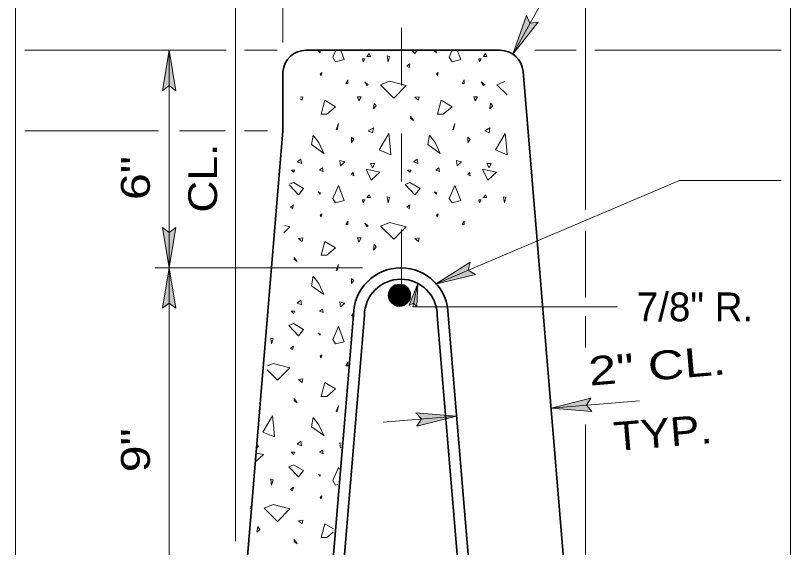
# Model space of a CAD drawing. Extents: x -9.07 to -2.08, y 8.04 to 17.77.
# Drawn here: x -6.811 to -5.197, y 15.562 to 16.67 of the extents above; entities that cross this region are included whole.
import ezdxf
from ezdxf.enums import TextEntityAlignment as Align

# ---------------------------------------------------------------- set-up
doc = ezdxf.new("R2010")
doc.units = 0
doc.header["$LTSCALE"] = 0.024
doc.linetypes.add('DOT_DASHED', pattern=[7.7, 5, -1.2, 0.3, -1.2])
for name, color, linetype, lineweight in [('1', 7, 'Continuous', 35), ('10', 7, 'Continuous', 13), ('12', 7, 'Continuous', 53), ('6', 7, 'Continuous', 13)]:
    doc.layers.add(name, color=color, linetype=linetype, lineweight=lineweight)

msp = doc.modelspace()

# ---------------------------------------------------------------- hatches: boundary and pattern name
at = {"layer": '10'}
for points in [[(-5.77533, 16.58917), (-5.72233, 16.65583), (-5.73967, 16.6535), (-5.74667, 16.66933)], [(-6.491, 16.59717), (-6.477, 16.51317), (-6.491, 16.52367), (-6.505, 16.51317)], [(-6.491, 16.14433), (-6.477, 16.22833), (-6.491, 16.21783), (-6.505, 16.22833)], [(-5.86433, 16.15633), (-5.93617, 16.11067), (-5.85333, 16.13067), (-5.8685, 16.1395)], [(-6.491, 16.14433), (-6.477, 16.06033), (-6.491, 16.07083), (-6.505, 16.06033)], [(-5.97333, 16.11167), (-5.97533, 16.063), (-5.982, 16.0705), (-5.991, 16.06633)], [(-5.6955, 15.85217), (-5.613, 15.87317), (-5.62233, 15.85833), (-5.61067, 15.84517)], [(-5.97733, 15.84267), (-5.89233, 15.83567), (-5.975, 15.81483), (-5.96567, 15.82967)]]:
    msp.add_hatch(color=256, dxfattribs=at).paths.add_polyline_path(points)

# ---------------------------------------------------------------- linework, layer by layer
at = {"layer": '1'}
for p, q in [((-6.206, 16.59717), (-5.80183, 16.59717)), ((-5.754, 16.55317), (-5.66, 15.4245)), ((-6.284, 13.922), (-6.107, 16.04583)), ((-6.26133, 13.922), (-6.08433, 16.04483)), ((-5.93267, 16.04483), (-5.75567, 13.922)), ((-5.91, 16.04583), (-5.73283, 13.922))]:
    msp.add_line(p, q, dxfattribs=at)
msp.add_lwpolyline([(-6.348, 15.30083), (-6.25383, 16.42933), (-6.25383, 16.55317)], dxfattribs=at)
for centre, radius in [((-6.01135, 16.08716), 0.02253), ((-6.01154, 16.08735), 0.02103), ((-6.01356, 16.08735), 0.01823), ((-6.01129, 16.08681), 0.02028), ((-6.01069, 16.08586), 0.01988), ((-6.01079, 16.08657), 0.0185), ((-6.01281, 16.08823), 0.01508), ((-6.0103, 16.08646), 0.01751), ((-6.01016, 16.08596), 0.0166), ((-6.00991, 16.08572), 0.01584), ((-6.01317, 16.08646), 0.01309), ((-6.01016, 16.08533), 0.0151), ((-6.0143, 16.08572), 0.01045), ((-6.00977, 16.08533), 0.01471), ((-6.01005, 16.08557), 0.01421), ((-6.00941, 16.08522), 0.01358), ((-6.00927, 16.08547), 0.01272), ((-6.01257, 16.08621), 0.00844), ((-6.00916, 16.08561), 0.01184), ((-6.00916, 16.08586), 0.01085), ((-6.00902, 16.08557), 0.01021), ((-6.00902, 16.08547), 0.00921), ((-6.00863, 16.08469), 0.00882), ((-6.00842, 16.08458), 0.00805), ((-6.00842, 16.08479), 0.00706), ((-6.00814, 16.08497), 0.00681), ((-6.00814, 16.08433), 0.00627), ((-6.00789, 16.08483), 0.00602), ((-6.00778, 16.08469), 0.00515), ((-6.00814, 16.08508), 0.0043), ((-6.00764, 16.08455), 0.00382), ((-6.0075, 16.08458), 0.00316), ((-6.00725, 16.08444), 0.00241), ((-6.00725, 16.08469), 0.00213), ((-6.00651, 16.08458), 0.00267), ((-6.00729, 16.08469), 0.00139), ((-6.00753, 16.08469), 0.000653), ((-6.007, 16.08469), 0.000415)]:
    msp.add_circle(centre, radius, dxfattribs=at)
for centre, radius, start, end in [((-6.20603, 16.54913), 0.04804, 90, 175.23532), ((-5.80188, 16.54913), 0.04804, 4.76467, 89.99999), ((-6.00847, 16.04581), 0.09853, 0, 180), ((-6.00847, 16.04487), 0.07581, 0, 180)]:
    msp.add_arc(centre, radius, start, end, dxfattribs=at)
at = {"layer": '10'}
for p, q in [((-6.81067, 17.69383), (-6.81067, 14.55983)), ((-5.624, 16.26517), (-5.624, 17.23967)), ((-5.67767, 16.765), (-5.77533, 16.58917)), ((-5.19733, 16.59683), (-5.19733, 16.705)), ((-5.74667, 16.66933), (-5.77533, 16.58917)), ((-5.74667, 16.66933), (-5.73967, 16.6535)), ((-5.72233, 16.65583), (-5.77533, 16.58917)), ((-5.72233, 16.65583), (-5.73967, 16.6535)), ((-6.37217, 16.59717), (-6.7915, 16.59717)), ((-6.505, 16.51317), (-6.491, 16.59717)), ((-6.491, 16.14433), (-6.491, 16.59717)), ((-6.477, 16.51317), (-6.491, 16.59717)), ((-6.266, 16.59717), (-6.33367, 16.59717)), ((-5.72983, 16.59717), (-5.64317, 16.59717)), ((-5.60483, 16.59717), (-5.2165, 16.59717)), ((-5.19733, 14.70767), (-5.19733, 16.59683)), ((-6.505, 16.51317), (-6.491, 16.52367)), ((-6.477, 16.51317), (-6.491, 16.52367)), ((-6.51267, 16.42933), (-6.7915, 16.42933)), ((-6.3745, 16.42933), (-6.46933, 16.42933)), ((-6.286, 16.42933), (-6.33367, 16.42933)), ((-5.42833, 16.32633), (-5.93617, 16.11067)), ((-5.42833, 16.32633), (-5.2165, 16.32633)), ((-6.505, 16.22833), (-6.491, 16.14433)), ((-6.505, 16.22833), (-6.491, 16.21783)), ((-6.477, 16.22833), (-6.491, 16.14433)), ((-6.477, 16.22833), (-6.491, 16.21783)), ((-5.624, 16.08233), (-5.624, 16.22167)), ((-5.86433, 16.15633), (-5.93617, 16.11067)), ((-5.86433, 16.15633), (-5.8685, 16.1395)), ((-6.0885, 16.14433), (-6.51983, 16.14433)), ((-6.505, 16.06033), (-6.491, 16.14433)), ((-6.477, 16.06033), (-6.491, 16.14433)), ((-6.491, 16.14433), (-6.491, 15.376)), ((-5.85333, 16.13067), (-5.8685, 16.1395)), ((-5.85333, 16.13067), (-5.93617, 16.11067)), ((-5.991, 16.06633), (-5.97333, 16.11167)), ((-5.97533, 16.063), (-5.97333, 16.11167)), ((-6.505, 16.06033), (-6.491, 16.07083)), ((-6.477, 16.06033), (-6.491, 16.07083)), ((-5.991, 16.06633), (-5.982, 16.0705)), ((-5.97533, 16.063), (-5.982, 16.0705)), ((-5.624, 15.97867), (-5.624, 16.04383)), ((-5.613, 15.87317), (-5.6955, 15.85217)), ((-5.6955, 15.85217), (-5.5115, 15.8675)), ((-5.613, 15.87317), (-5.62233, 15.85833)), ((-5.61067, 15.84517), (-5.6955, 15.85217)), ((-5.61067, 15.84517), (-5.62233, 15.85833)), ((-6.045, 15.823), (-5.89233, 15.83567)), ((-5.97733, 15.84267), (-5.89233, 15.83567)), ((-5.97733, 15.84267), (-5.96567, 15.82967)), ((-5.975, 15.81483), (-5.89233, 15.83567)), ((-5.975, 15.81483), (-5.96567, 15.82967)), ((-5.624, 15.34), (-5.624, 15.8185))]:
    msp.add_line(p, q, dxfattribs=at)
at = {"layer": '10', "linetype": 'DOT_DASHED'}
msp.add_line((-6.00733, 16.10383), (-6.00733, 16.94883), dxfattribs=at)
at = {"layer": '10'}
for points in [[(-6.25383, 16.61317), (-6.25383, 16.707), (-6.25383, 17.4055)], [(-6.353, 17.23967), (-6.353, 16.5955), (-6.353, 15.57517)], [(-5.5575, 16.063), (-5.9835, 16.063), (-5.97333, 16.11167)]]:
    msp.add_lwpolyline(points, dxfattribs=at)
for points in [[(-5.77533, 16.58917), (-5.72233, 16.65583), (-5.73967, 16.6535), (-5.74667, 16.66933)], [(-6.491, 16.59717), (-6.477, 16.51317), (-6.491, 16.52367), (-6.505, 16.51317)], [(-6.491, 16.14433), (-6.477, 16.22833), (-6.491, 16.21783), (-6.505, 16.22833)], [(-5.86433, 16.15633), (-5.93617, 16.11067), (-5.85333, 16.13067), (-5.8685, 16.1395)], [(-6.491, 16.14433), (-6.477, 16.06033), (-6.491, 16.07083), (-6.505, 16.06033)], [(-5.97333, 16.11167), (-5.97533, 16.063), (-5.982, 16.0705), (-5.991, 16.06633)], [(-5.6955, 15.85217), (-5.613, 15.87317), (-5.62233, 15.85833), (-5.61067, 15.84517)], [(-5.97733, 15.84267), (-5.89233, 15.83567), (-5.975, 15.81483), (-5.96567, 15.82967)]]:
    msp.add_lwpolyline(points, close=True, dxfattribs=at)
at = {"layer": '6'}
for points in [[(-6.17633, 16.59467), (-6.1805, 16.59617), (-6.17633, 16.59183)], [(-6.07467, 16.59033), (-6.0715, 16.58433), (-6.079, 16.58433)], [(-6.03683, 16.58567), (-6.03517, 16.5735), (-6.03217, 16.58433)], [(-5.934, 16.59467), (-5.93833, 16.59617), (-5.934, 16.59183)], [(-5.83233, 16.59033), (-5.82917, 16.58433), (-5.83667, 16.58433)], [(-6.08833, 16.5795), (-6.087, 16.5735), (-6.08367, 16.5795)], [(-5.99583, 16.5645), (-5.9915, 16.5615), (-5.98967, 16.56917)], [(-5.846, 16.5795), (-5.84467, 16.5735), (-5.84133, 16.5795)], [(-6.173, 16.55083), (-6.17633, 16.54783), (-6.1745, 16.54467)], [(-5.93067, 16.55083), (-5.934, 16.54783), (-5.93217, 16.54467)], [(-6.11867, 16.53567), (-6.123, 16.52817), (-6.11867, 16.52817)], [(-6.079, 16.52383), (-6.07617, 16.52517), (-6.08367, 16.53133)], [(-6.03217, 16.53283), (-5.99733, 16.52383), (-6.02317, 16.49783), (-6.05067, 16.52517)], [(-5.87633, 16.53567), (-5.88067, 16.52817), (-5.87633, 16.52817)], [(-5.83667, 16.52383), (-5.83383, 16.52517), (-5.84133, 16.53133)], [(-6.1625, 16.46433), (-6.14417, 16.47983), (-6.16683, 16.49317), (-6.1745, 16.46433)], [(-6.09883, 16.50067), (-6.096, 16.49167), (-6.09133, 16.50067)], [(-5.97933, 16.49933), (-5.97167, 16.49317), (-5.97033, 16.50067)], [(-5.92033, 16.46433), (-5.90183, 16.47983), (-5.9245, 16.49317), (-5.93217, 16.46433)], [(-5.8565, 16.50067), (-5.85367, 16.49167), (-5.849, 16.50067)], [(-6.06383, 16.48733), (-6.06567, 16.47517), (-6.05967, 16.48133)], [(-5.82167, 16.48733), (-5.82333, 16.47517), (-5.81733, 16.48133)], [(-5.98833, 16.46), (-5.98833, 16.45533), (-5.98217, 16.451)], [(-6.14283, 16.43267), (-6.14133, 16.43267), (-6.1385, 16.44483)], [(-5.9005, 16.43267), (-5.899, 16.43267), (-5.89617, 16.44483)], [(-6.07617, 16.42983), (-6.06717, 16.42517), (-6.06567, 16.43583)], [(-5.83383, 16.42983), (-5.82483, 16.42517), (-5.82333, 16.43583)], [(-6.19133, 16.4205), (-6.19433, 16.401), (-6.16867, 16.38267), (-6.17917, 16.40533)], [(-6.111, 16.41617), (-6.111, 16.40533), (-6.10633, 16.4115)], [(-6.03083, 16.39767), (-6.02933, 16.37967), (-6.0535, 16.39017), (-6.03367, 16.42367)], [(-5.949, 16.4205), (-5.952, 16.401), (-5.92633, 16.38267), (-5.93683, 16.40533)], [(-5.86883, 16.41617), (-5.86883, 16.40533), (-5.864, 16.4115)], [(-5.7885, 16.39767), (-5.787, 16.37967), (-5.81117, 16.39017), (-5.79133, 16.42367)], [(-6.217, 16.37067), (-6.2245, 16.36467), (-6.2155, 16.36133)], [(-6.13517, 16.3675), (-6.13383, 16.357), (-6.12483, 16.36467)], [(-6.0715, 16.36133), (-6.06717, 16.35233), (-6.0625, 16.36133)], [(-5.97467, 16.37067), (-5.98217, 16.36467), (-5.97317, 16.36133)], [(-5.89283, 16.3675), (-5.8915, 16.357), (-5.8825, 16.36467)], [(-5.82917, 16.36133), (-5.82483, 16.35233), (-5.82017, 16.36133)], [(-6.17767, 16.348), (-6.17017, 16.34483), (-6.1715, 16.35233)], [(-6.111, 16.33867), (-6.10633, 16.33583), (-6.10783, 16.34333)], [(-6.08083, 16.3495), (-6.07, 16.32683), (-6.052, 16.34333)], [(-5.9945, 16.348), (-5.98967, 16.34333), (-5.98683, 16.348)], [(-5.93533, 16.348), (-5.92783, 16.34483), (-5.92933, 16.35233)], [(-5.86883, 16.33867), (-5.864, 16.33583), (-5.8655, 16.34333)], [(-5.8385, 16.3495), (-5.82767, 16.32683), (-5.80967, 16.34333)], [(-6.14417, 16.27967), (-6.12617, 16.28433), (-6.1385, 16.316), (-6.15033, 16.289)], [(-5.99917, 16.31783), (-5.97933, 16.2965), (-5.9685, 16.30983), (-5.98967, 16.32217)], [(-5.90183, 16.27967), (-5.88383, 16.28433), (-5.89617, 16.316), (-5.908, 16.289)], [(-6.17633, 16.30083), (-6.1805, 16.30233), (-6.17633, 16.298)], [(-6.07467, 16.2965), (-6.0715, 16.2905), (-6.079, 16.2905)], [(-5.934, 16.30083), (-5.93833, 16.30233), (-5.934, 16.298)], [(-5.83233, 16.2965), (-5.82917, 16.2905), (-5.83667, 16.2905)], [(-6.08833, 16.28583), (-6.087, 16.27967), (-6.08367, 16.28583)], [(-6.03683, 16.29183), (-6.03517, 16.27967), (-6.03217, 16.2905)], [(-5.846, 16.28583), (-5.84467, 16.27967), (-5.84133, 16.28583)], [(-5.79467, 16.29183), (-5.79283, 16.27967), (-5.78983, 16.2905)], [(-6.23817, 16.27067), (-6.23383, 16.26783), (-6.232, 16.27533)], [(-5.99583, 16.27067), (-5.9915, 16.26783), (-5.98967, 16.27533)], [(-6.173, 16.257), (-6.17633, 16.25417), (-6.1745, 16.25083)], [(-5.93067, 16.257), (-5.934, 16.25417), (-5.93217, 16.25083)], [(-6.11867, 16.24183), (-6.123, 16.23433), (-6.11867, 16.23433)], [(-6.079, 16.23), (-6.07617, 16.23133), (-6.08367, 16.2375)], [(-6.03217, 16.239), (-5.99733, 16.23), (-6.02317, 16.204), (-6.05067, 16.23133)], [(-5.87633, 16.24183), (-5.88067, 16.23433), (-5.87633, 16.23433)], [(-6.22167, 16.2055), (-6.214, 16.19933), (-6.21267, 16.207)], [(-6.1625, 16.1705), (-6.14417, 16.186), (-6.16683, 16.19933), (-6.1745, 16.1705)], [(-6.09883, 16.207), (-6.096, 16.19783), (-6.09133, 16.207)], [(-5.97933, 16.2055), (-5.97167, 16.19933), (-5.97033, 16.207)], [(-6.06383, 16.19367), (-6.06567, 16.18133), (-6.05967, 16.1875)], [(-6.23067, 16.16617), (-6.23067, 16.1615), (-6.2245, 16.15717)], [(-6.14283, 16.13883), (-6.14133, 16.13883), (-6.1385, 16.15117)], [(-6.19133, 16.12667), (-6.19433, 16.10717), (-6.16867, 16.08883), (-6.17917, 16.1115)], [(-6.111, 16.12233), (-6.111, 16.1115), (-6.10633, 16.11767)], [(-6.217, 16.077), (-6.2245, 16.07083), (-6.2155, 16.0675)], [(-6.13517, 16.07367), (-6.13383, 16.06333), (-6.12483, 16.07083)], [(-6.23667, 16.05433), (-6.232, 16.0495), (-6.22917, 16.05433)], [(-6.17767, 16.05433), (-6.17017, 16.051), (-6.1715, 16.0585)], [(-6.2415, 16.024), (-6.22167, 16.00283), (-6.21083, 16.01617), (-6.232, 16.02833)], [(-6.14417, 15.98583), (-6.12617, 15.9905), (-6.1385, 16.02217), (-6.15033, 15.99517)], [(-6.17633, 16.00717), (-6.1805, 16.0085), (-6.17633, 16.00417)], [(-6.23817, 15.97683), (-6.23383, 15.974), (-6.232, 15.9815)], [(-6.173, 15.96317), (-6.17633, 15.96033), (-6.1745, 15.957)], [(-6.11867, 15.948), (-6.123, 15.9405), (-6.11867, 15.9405)], [(-6.22167, 15.91167), (-6.214, 15.9055), (-6.21267, 15.91317)], [(-6.1625, 15.87667), (-6.14417, 15.89217), (-6.16683, 15.9055), (-6.1745, 15.87667)], [(-6.23067, 15.8725), (-6.23067, 15.86767), (-6.2245, 15.8635)], [(-6.14283, 15.845), (-6.14133, 15.845), (-6.1385, 15.85733)], [(-6.27317, 15.81017), (-6.27167, 15.79217), (-6.29583, 15.8025), (-6.276, 15.836)], [(-6.19133, 15.83283), (-6.19433, 15.81333), (-6.16867, 15.795), (-6.17917, 15.81767)], [(-6.217, 15.78317), (-6.2245, 15.777), (-6.2155, 15.77383)], [(-6.17767, 15.7605), (-6.17017, 15.75717), (-6.1715, 15.76483)], [(-6.23667, 15.7605), (-6.232, 15.75583), (-6.22917, 15.7605)], [(-6.2415, 15.73017), (-6.22167, 15.709), (-6.21083, 15.72233), (-6.232, 15.7345)], [(-6.17633, 15.71333), (-6.1805, 15.71467), (-6.17633, 15.71033)], [(-6.27917, 15.70433), (-6.2775, 15.692), (-6.2745, 15.70283)], [(-6.23817, 15.683), (-6.23383, 15.68017), (-6.232, 15.68767)], [(-6.173, 15.66933), (-6.17633, 15.6665), (-6.1745, 15.66317)], [(-6.2745, 15.65133), (-6.23967, 15.64233), (-6.2655, 15.6165), (-6.29283, 15.64383)], [(-6.22167, 15.61783), (-6.214, 15.61167), (-6.21267, 15.61933)], [(-6.30617, 15.606), (-6.308, 15.59367), (-6.30183, 15.59983)], [(-6.23067, 15.57867), (-6.23067, 15.574), (-6.2245, 15.56967)]]:
    msp.add_lwpolyline(points, close=True, dxfattribs=at)
for points in [[(-6.144, 16.59717), (-6.15033, 16.58283), (-6.14417, 16.5735), (-6.12617, 16.57817), (-6.1335, 16.59717)], [(-5.98567, 16.59717), (-5.97933, 16.59033), (-5.97383, 16.59717)], [(-5.90167, 16.59717), (-5.908, 16.58283), (-5.90183, 16.5735), (-5.88383, 16.57817), (-5.89117, 16.59717)], [(-5.78733, 16.50433), (-5.80833, 16.52517), (-5.79167, 16.532)], [(-6.21833, 16.4965), (-6.214, 16.49317), (-6.21267, 16.50067), (-6.21783, 16.49983)], [(-6.23633, 16.34767), (-6.232, 16.34333), (-6.22917, 16.348), (-6.23633, 16.348)], [(-6.24017, 16.3165), (-6.22167, 16.2965), (-6.21083, 16.30983), (-6.232, 16.32217), (-6.24, 16.3185)], [(-6.25033, 16.23267), (-6.23967, 16.23), (-6.25233, 16.21733)], [(-6.107, 16.04533), (-6.10783, 16.0495), (-6.111, 16.04483), (-6.10733, 16.0425)], [(-6.279, 15.997), (-6.2775, 15.98583), (-6.2745, 15.99667), (-6.279, 15.998)], [(-6.286, 15.9405), (-6.2745, 15.94517), (-6.23967, 15.93617), (-6.2655, 15.91017), (-6.287, 15.93167)], [(-6.132, 15.779), (-6.13517, 15.77983), (-6.13383, 15.7695), (-6.13283, 15.77017)], [(-6.30667, 15.77017), (-6.30483, 15.77383), (-6.30633, 15.77383)], [(-6.31017, 15.74117), (-6.29433, 15.75583), (-6.30817, 15.75867)], [(-6.13717, 15.72483), (-6.1385, 15.72833), (-6.15033, 15.70133), (-6.14417, 15.692), (-6.14, 15.69317)], [(-6.31467, 15.7045), (-6.31383, 15.70283), (-6.31483, 15.70283)], [(-6.32217, 15.64367), (-6.32133, 15.64233), (-6.3185, 15.64383), (-6.32183, 15.6465)], [(-6.14867, 15.601), (-6.16683, 15.61167), (-6.1745, 15.583), (-6.1625, 15.583), (-6.14933, 15.59417)]]:
    msp.add_lwpolyline(points, dxfattribs=at)

# ---------------------------------------------------------------- texts
at = {"layer": '12'}
for s, rotation, width, p in [('CL.', 90, 1.15, (-6.391, 16.33108)), ('6"', 90, 1.25, (-6.531, 16.33117)), ('2" CL.', 4.764, 1.3, (-5.47245, 15.91085)), ('TYP.', 4.764, 1.15, (-5.46083, 15.77129)), ('9"', 90, 1.25, (-6.531, 15.76442))]:
    msp.add_text(s, height=0.06001, rotation=rotation, dxfattribs=dict(at, width=width)).set_placement(p, align=Align.CENTER)
msp.add_text('7/8" R.', height=0.06001, dxfattribs=at).set_placement((-5.51742, 16.033))

doc.saveas('drawing.dxf')
